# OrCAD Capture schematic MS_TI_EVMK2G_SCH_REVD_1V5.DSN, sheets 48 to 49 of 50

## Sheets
48 47. PMIC POWER CIRCUIT1: size C; title: PMIC POWER CIRCUIT 1
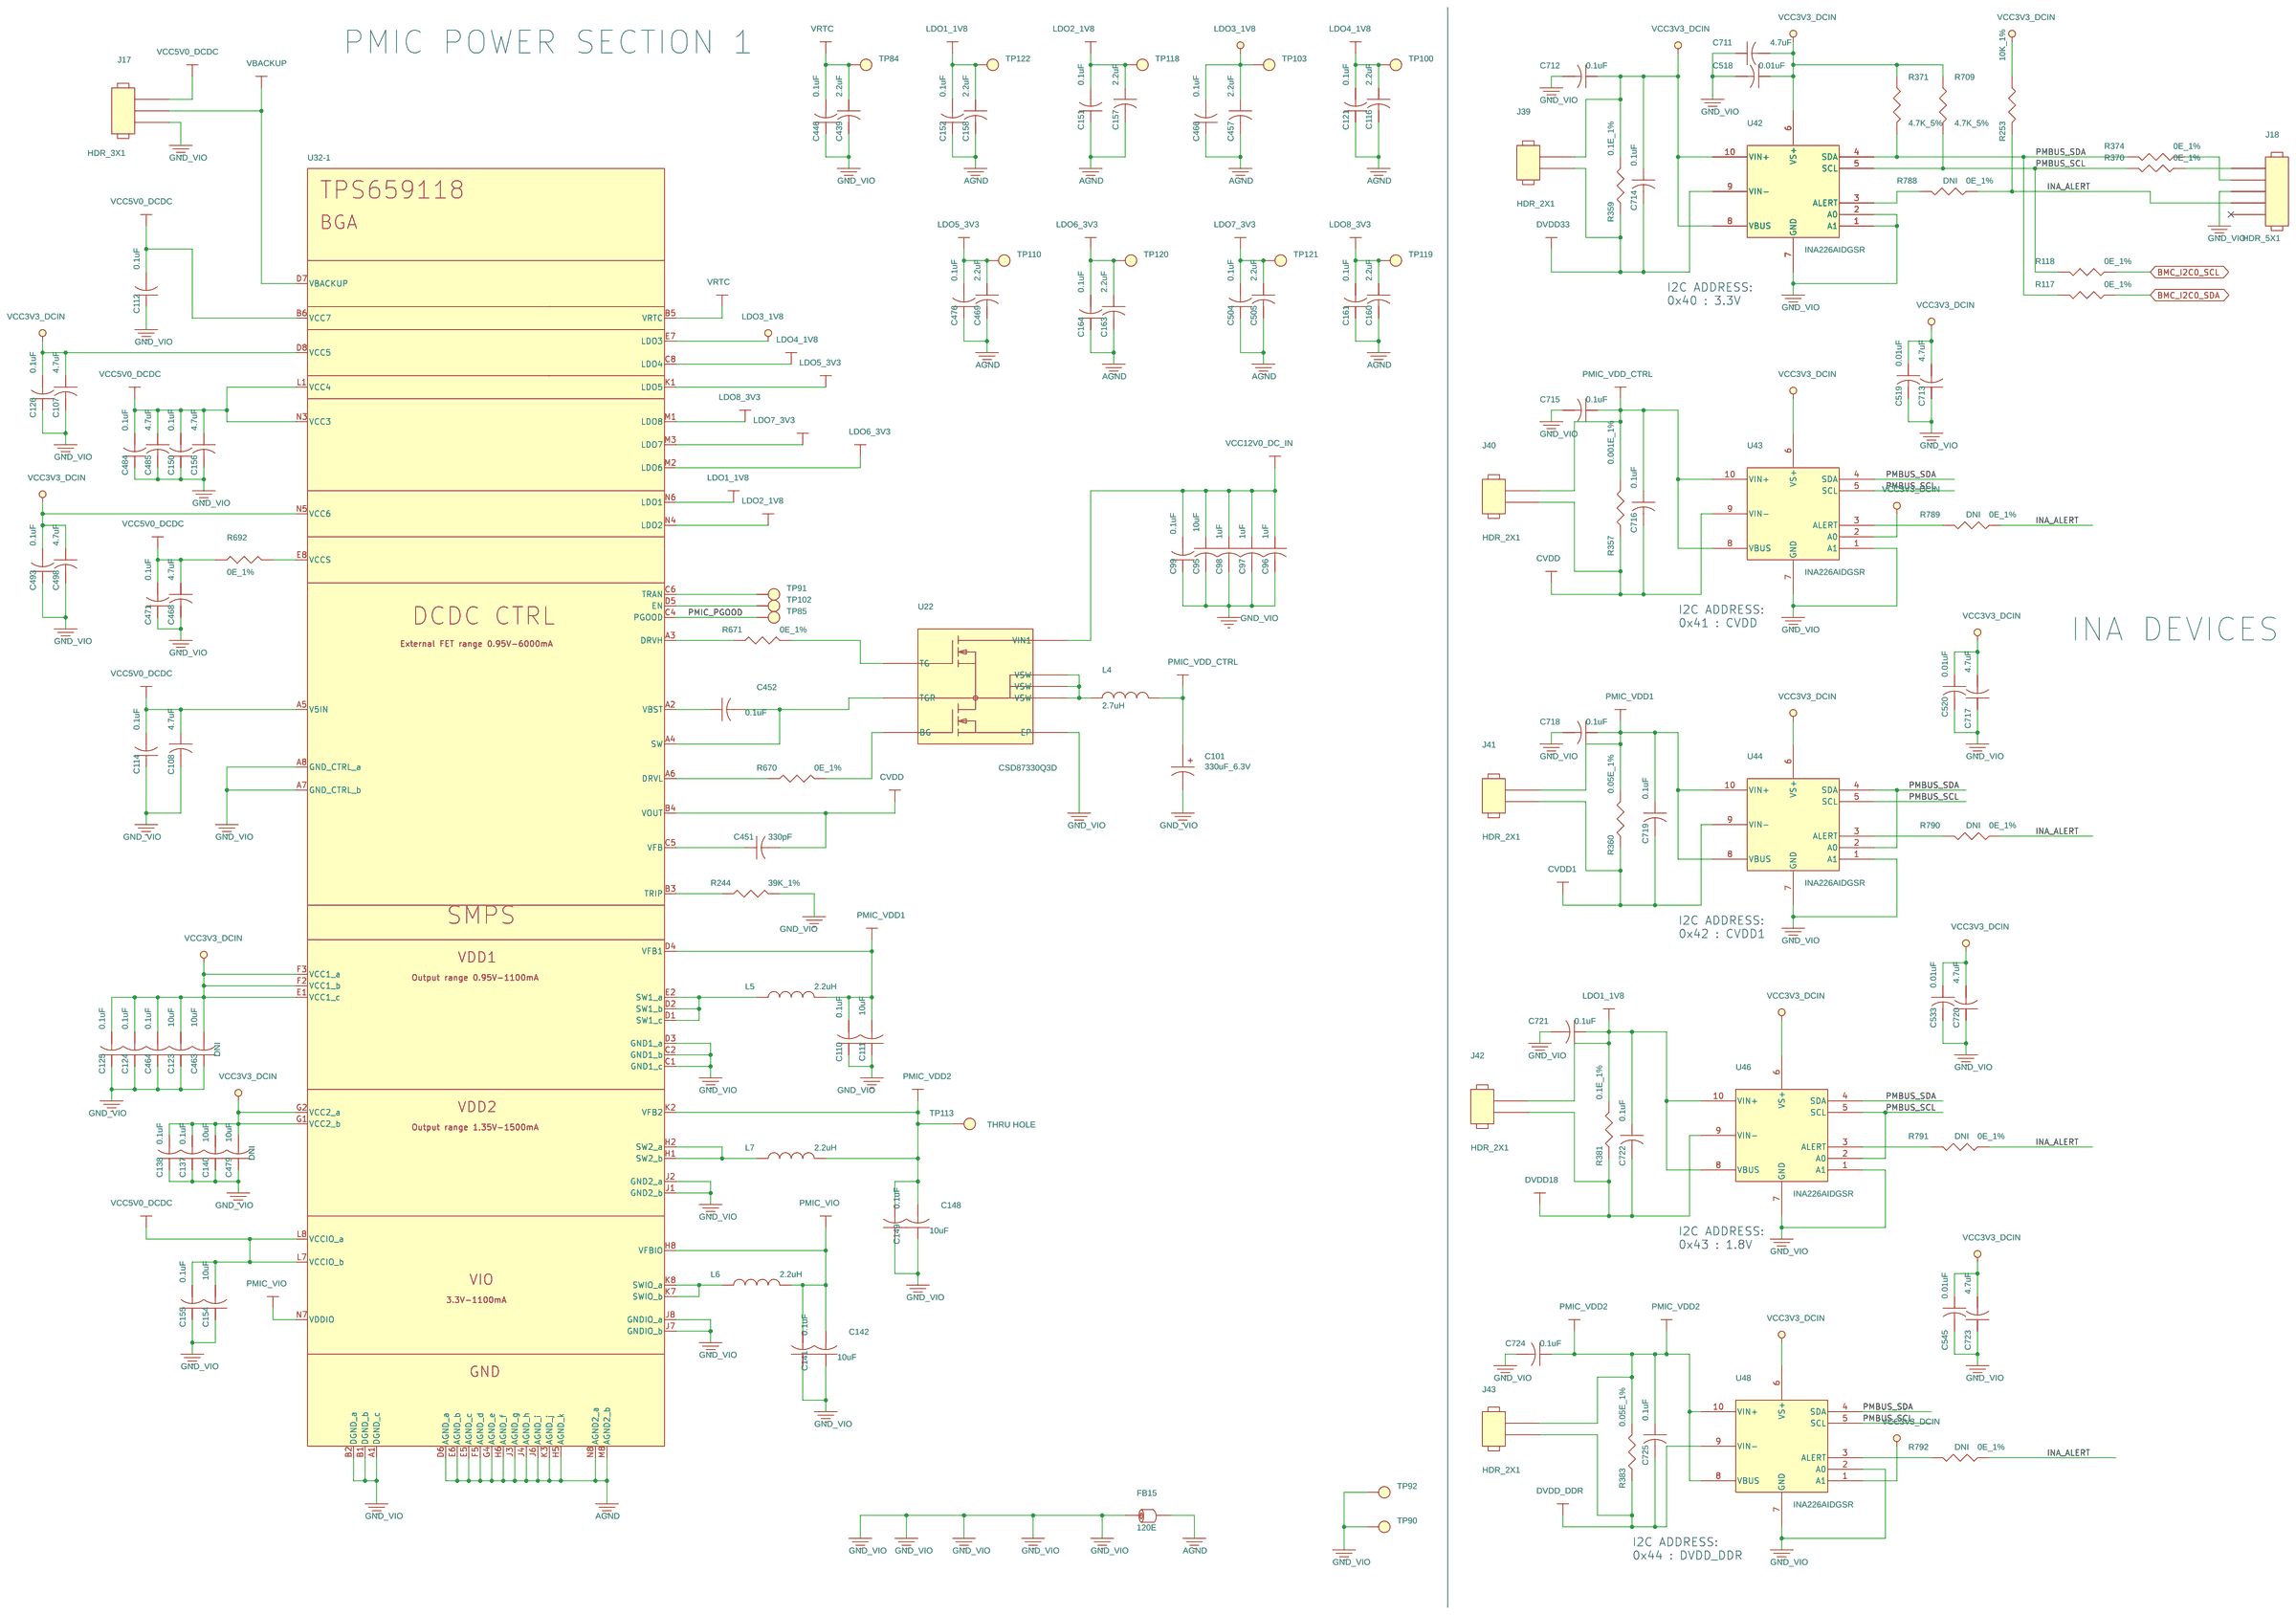
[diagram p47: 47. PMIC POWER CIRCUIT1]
49 48. PMIC POWER CIRCUIT2: size C; title: PMIC POWER CIRCUIT 2
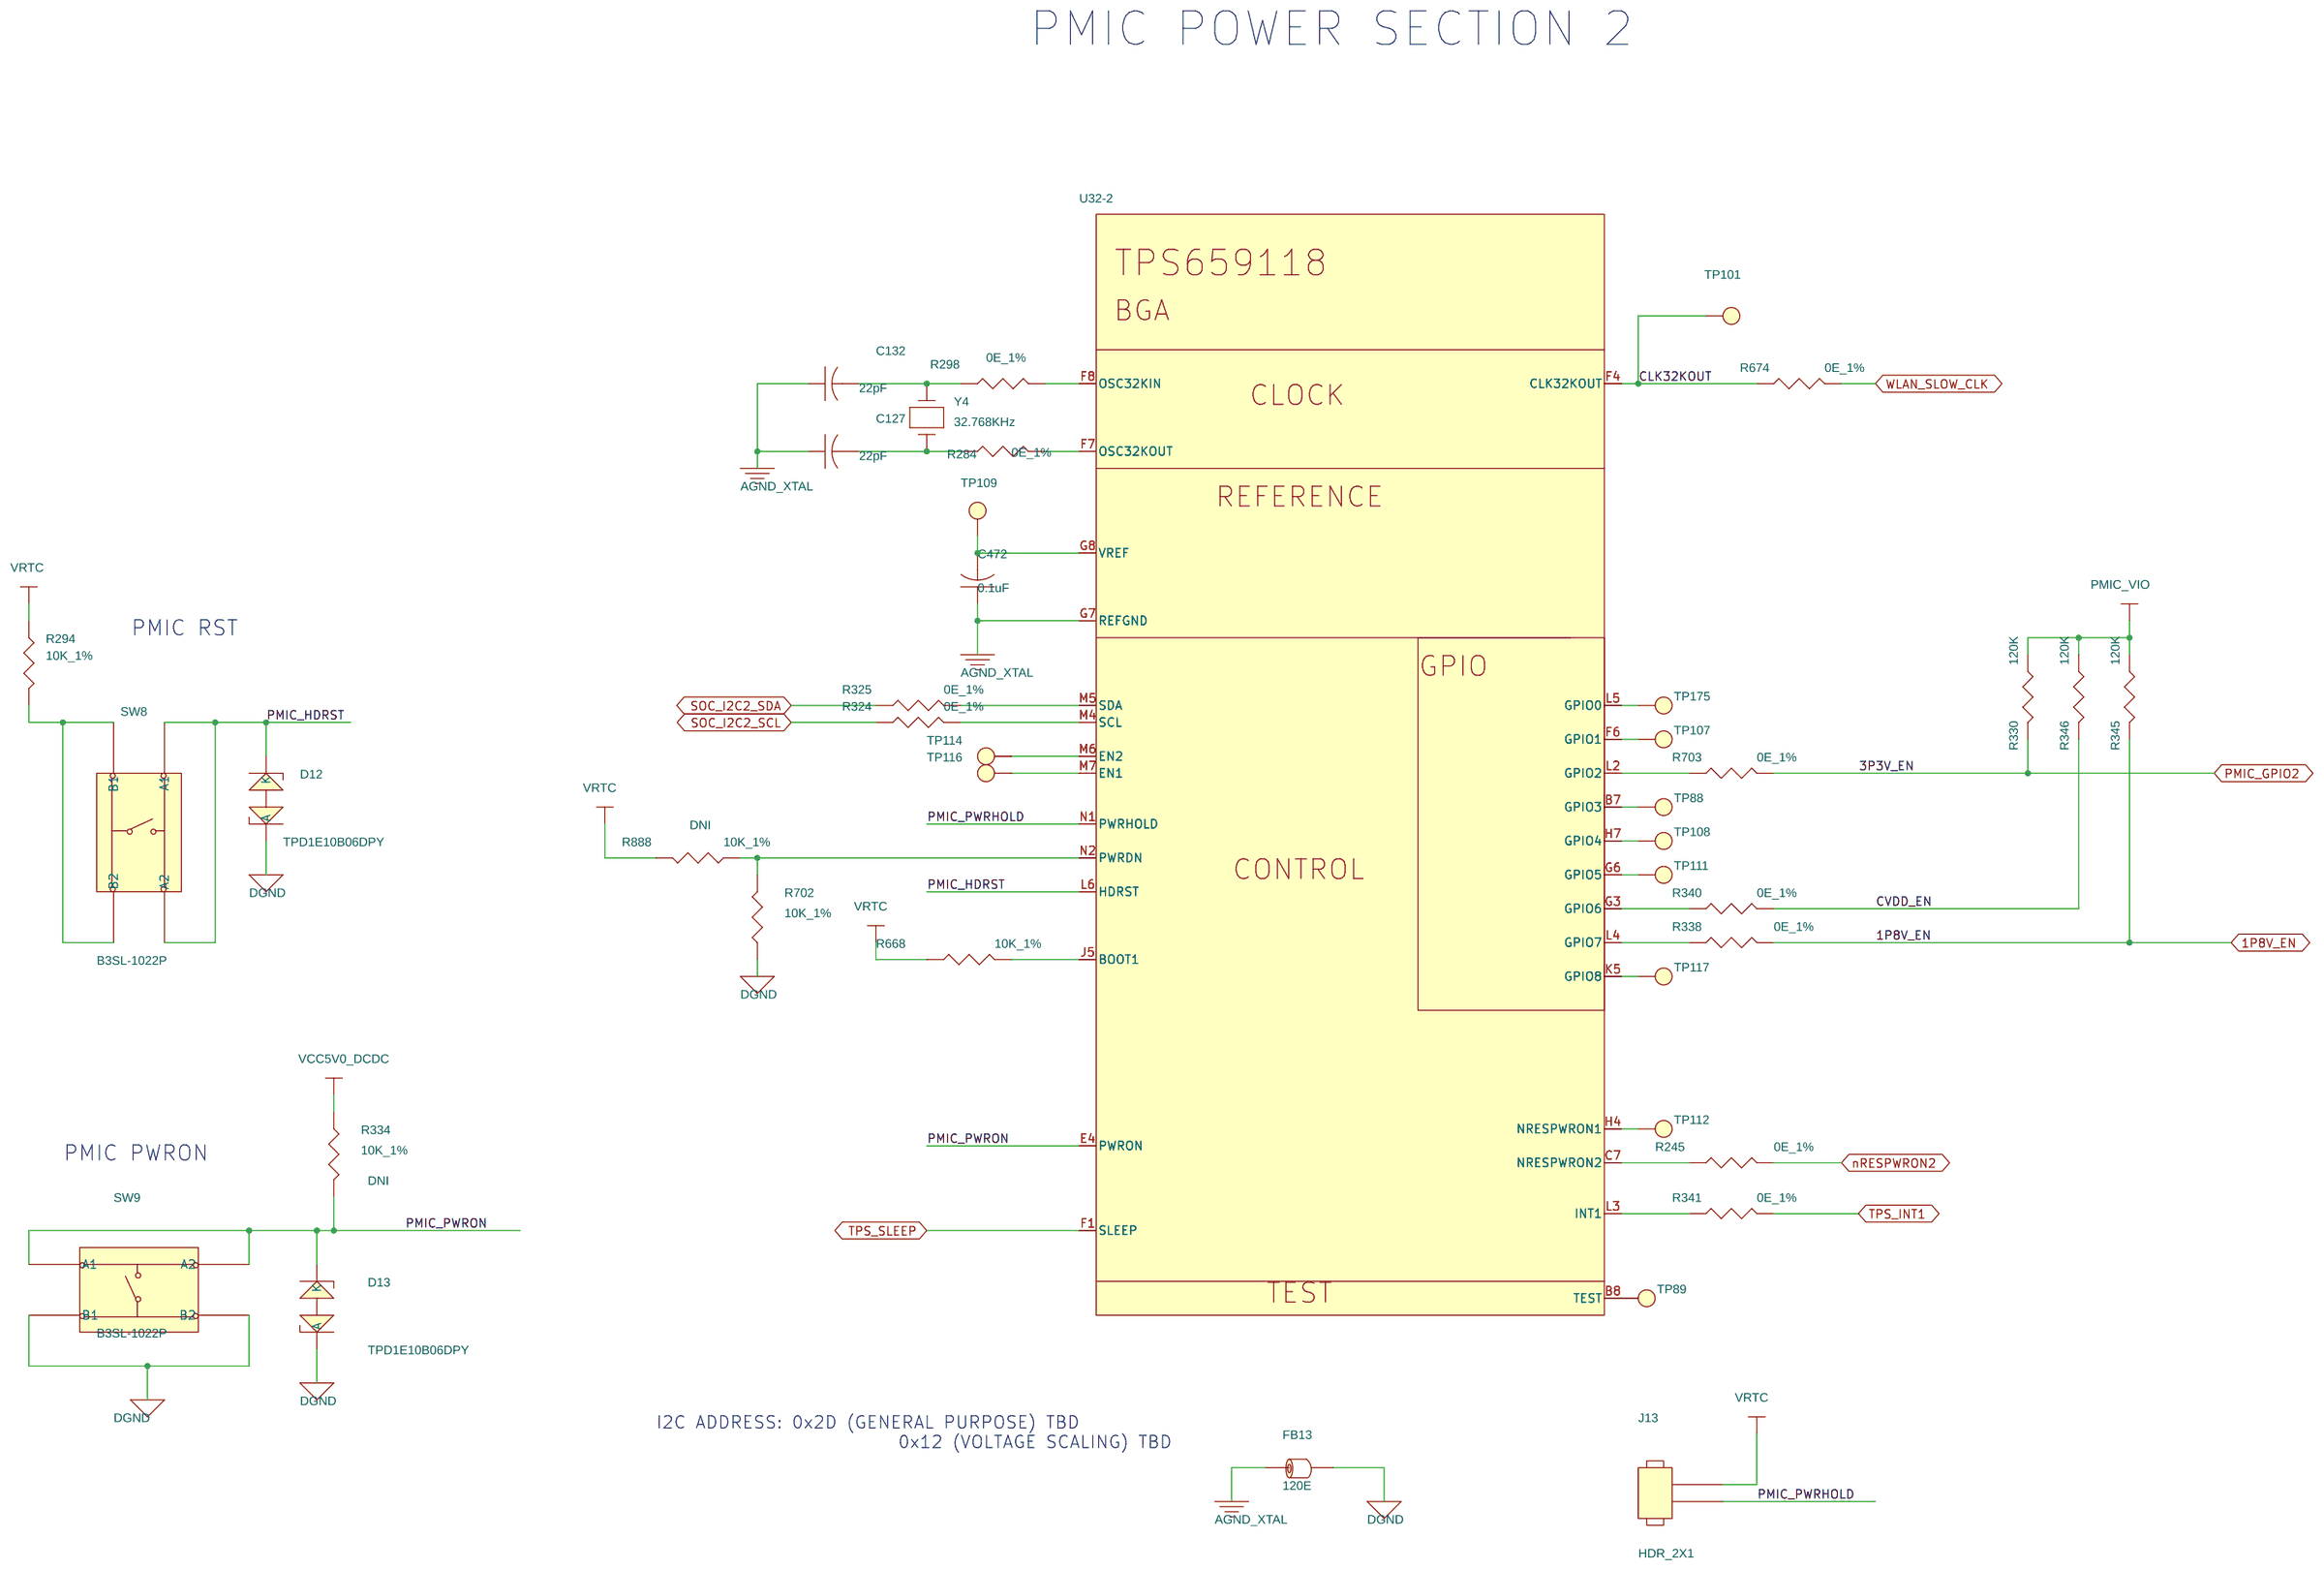
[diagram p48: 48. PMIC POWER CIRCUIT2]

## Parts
sheet 47. PMIC POWER CIRCUIT1
C95  10uF  [CAP1210]
C96  1uF  [CAP0603]
C97  1uF  [CAP0603]
C98  1uF  [CAP0603]
C99  0.1uF  [CAP0402]
C101  330uF_6.3V  [CAPT7343D]
C107  4.7uF  [CAP1206]
C108  4.7uF  [CAP1206]
C110  0.1uF  [CAP0402]
C111  10uF  [CAP0805]
C112  0.1uF  [CAP0402]
C114  0.1uF  [CAP0402]
C116  2.2uF  [CAP0402]
C121  0.1uF  [CAP0402]
C123  10uF  [CAP0805]
C124  0.1uF  [CAP0402]
C125  0.1uF  [CAP0402]
C126  0.1uF  [CAP0402]
C137  0.1uF  [CAP0402]
C138  0.1uF  [CAP0402]
C140  10uF  [CAP0805]
C141  0.1uF  [CAP0402]
C142  10uF  [CAP0805]
C148  10uF  [CAP0805]
C149  0.1uF  [CAP0402]
C150  0.1uF  [CAP0402]
C151  0.1uF  [CAP0402]
C152  0.1uF  [CAP0402]
C154  10uF  [CAP0805]
C155  0.1uF  [CAP0402]
C156  4.7uF  [CAP1206]
C157  2.2uF  [CAP0402]
C158  2.2uF  [CAP0402]
C160  2.2uF  [CAP0402]
C161  0.1uF  [CAP0402]
C163  2.2uF  [CAP0402]
C164  0.1uF  [CAP0402]
C439  2.2uF  [CAP0402]
C446  0.1uF  [CAP0402]
C451  330pF  [CAP0402]
C452  0.1uF  [CAP0402]
C457  2.2uF  [CAP0402]
C463  10uF  [CAP0805]
C464  0.1uF  [CAP0402]
C466  0.1uF  [CAP0402]
C468  4.7uF  [CAP1206]
C469  2.2uF  [CAP0402]
C471  0.1uF  [CAP0402]
C476  0.1uF  [CAP0402]
C479  10uF  [CAP0805]
C484  0.1uF  [CAP0402]
C485  4.7uF  [CAP1206]
C493  0.1uF  [CAP0402]
C498  4.7uF  [CAP1206]
C504  0.1uF  [CAP0402]
C505  2.2uF  [CAP0402]
C518  0.01uF  [CAP0402]
C519  0.01uF  [CAP0402]
C520  0.01uF  [CAP0402]
C533  0.01uF  [CAP0402]
C545  0.01uF  [CAP0402]
C711  4.7uF  [CAP0603]
C712  0.1uF  [CAP0402]
C713  4.7uF  [CAP0603]
C714  0.1uF  [CAP0402]
C715  0.1uF  [CAP0402]
C716  0.1uF  [CAP0402]
C717  4.7uF  [CAP0603]
C718  0.1uF  [CAP0402]
C719  0.1uF  [CAP0402]
C720  4.7uF  [CAP0603]
C721  0.1uF  [CAP0402]
C722  0.1uF  [CAP0402]
C723  4.7uF  [CAP0603]
C724  0.1uF  [CAP0402]
C725  0.1uF  [CAP0402]
FB15  120E  [IND0402]
J17  HDR_3X1  [HDR_3X1_100_S_T]
J18  HDR_5X1  [HDR_5X1_100_S_T]
J39  HDR_2X1  [HDR_2X1_100_S_T]
J40  HDR_2X1  [HDR_2X1_100_S_T]
J41  HDR_2X1  [HDR_2X1_100_S_T]
J42  HDR_2X1  [HDR_2X1_100_S_T]
J43  HDR_2X1  [HDR_2X1_100_S_T]
L4  2.7uH  [IND_XAL7030_315X315_SMD]
L5  2.2uH  [IND_VLCF5020T_205X210_SMD]
L6  2.2uH  [IND_VLCF5020T_205X210_SMD]
L7  2.2uH  [IND_VLCF5020T_205X210_SMD]
R117  0E_1%  [RES0402]
R118  0E_1%  [RES0402]
R244  39K_1%  [RES0603]
R253  10K_1%  [RES0402]
R357  0.001E_1%  [RES2725]
R359  0.1E_1%  [RES1210]
R360  0.05E_1%  [RES1812]
R370  0E_1%  [RES0402]
R371  4.7K_5%  [RES0402]
R374  0E_1%  [RES0402]
R381  0.1E_1%  [RES1210]
R383  0.05E_1%  [RES1812]
R670  0E_1%  [RES0402]
R671  0E_1%  [RES0402]
R692  0E_1%  [RES0402]
R709  4.7K_5%  [RES0402]
R788  0E_1%  [RES0402]
R789  0E_1%  [RES0402]
R790  0E_1%  [RES0402]
R791  0E_1%  [RES0402]
R792  0E_1%  [RES0402]
TP84  THRU HOLE  [TP_40X65]
TP85  THRU HOLE  [TP_40X65]
TP90  THRU HOLE  [TP_40X65]
TP91  THRU HOLE  [TP_40X65]
TP92  THRU HOLE  [TP_40X65]
TP100  THRU HOLE  [TP_40X65]
TP102  THRU HOLE  [TP_40X65]
TP103  THRU HOLE  [TP_40X65]
TP110  THRU HOLE  [TP_40X65]
TP113  THRU HOLE  [TP_40X80]
TP118  THRU HOLE  [TP_40X65]
TP119  THRU HOLE  [TP_40X65]
TP120  THRU HOLE  [TP_40X65]
TP121  THRU HOLE  [TP_40X65]
TP122  THRU HOLE  [TP_40X65]
U22  CSD87330Q3D  [SON8_25-59_130X130_TI]
U42  INA226AIDGSR  [MSOP10_19-68_120X120]
U43  INA226AIDGSR  [MSOP10_19-68_120X120]
U44  INA226AIDGSR  [MSOP10_19-68_120X120]
U46  INA226AIDGSR  [MSOP10_19-68_120X120]
U48  INA226AIDGSR  [MSOP10_19-68_120X120]
sheet 48. PMIC POWER CIRCUIT2
C127  22pF  [CAP0402]
C132  22pF  [CAP0402]
C472  0.1uF  [CAP0402]
D12  TPD1E10B06DPY  [DIO_DFN0402]
D13  TPD1E10B06DPY  [DIO_DFN0402]
FB13  120E  [IND0402]
J13  HDR_2X1  [HDR_2X1_100_S_T]
R245  0E_1%  [RES0402]
R284  0E_1%  [RES0402]
R294  10K_1%  [RES0402]
R298  0E_1%  [RES0402]
R324  0E_1%  [RES0402]
R325  0E_1%  [RES0402]
R330  120K  [RES0603]
R334  10K_1%  [RES0402]
R338  0E_1%  [RES0402]
R340  0E_1%  [RES0402]
R341  0E_1%  [RES0402]
R345  120K  [RES0603]
R346  120K  [RES0603]
R668  10K_1%  [RES0402]
R674  0E_1%  [RES0402]
R702  10K_1%  [RES0402]
R703  0E_1%  [RES0402]
R888  10K_1%  [RES0402]
SW8  B3SL-1022P  [SW4_EVQQ2_255X240_SMD]
SW9  B3SL-1022P  [SW4_EVQQ2_255X240_SMD]
TP88  THRU HOLE  [TP_40X65]
TP89  THRU HOLE  [TP_40X65]
TP101  THRU HOLE  [TP_40X65]
TP107  THRU HOLE  [TP_40X65]
TP108  THRU HOLE  [TP_40X65]
TP109  THRU HOLE  [TP_40X65]
TP111  THRU HOLE  [TP_40X65]
TP112  THRU HOLE  [TP_40X65]
TP114  THRU HOLE  [TP_40X65]
TP116  THRU HOLE  [TP_40X65]
TP117  THRU HOLE  [TP_40X65]
TP175  THRU HOLE  [TP_40X65]
U32  PTPS659113A2ZRC  [BGA98_25-59_360x240]  (sections -1,-2)
Y4  32.768KHz  [XTAL_FC-135_130X65_SMD]

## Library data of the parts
C95 = CAP: CAP CERAMIC 10uF 25V 20% X7R 1210; Chkd/date: SHREESHAIL/200707; Crtd /date: MAZHAR/180707; Custom_Duty: 15%; Customs_HS_Code: 85322990; Distributor_name: DIGIKEY; Distributor_part_number: 445-1434-1-ND; Height: 2.80MM; Mfr_name: TDK CORPORATION; Mfr_part_number: C3225X7R1E106M; Mistral Part No: 120009030191-R; Package: 1210; Part_type: CAPACITORS\CERAMIC; Project: REVA-IBMS; RoHS: RoHS; Tolerance: 20%; Voltage: 25V; Datasheet: Y:\MIS_DATABASE\DATASHEETS\CAPACITORS\TDK_CAP.PDF
C96-C98 = CAP: CAP CERAMIC 1uF 25V 10% X7R 0603; Chkd/date: BAVISH/040311; Crtd /date: MAZHAR/190111; Custom_Duty: 15%; Customs_HS_Code: 85322990; Distributor_name: DIGIKEY; Distributor_part_number: 490-5307-1-ND; Height: 0.90MM; Mfr_name: MURATA; Mfr_part_number: GRM188R71E105KA12D; Mistral Part No: 120011010017-R; Package: 0603; Part_type: CAPACITORS\CERAMIC; Project: ITS-PWR_CARD; RoHS: RoHS; Temperature: -55°C+125°C; Tolerance: 10%; Voltage: 25V; Wattage: NA; Weight: NA; Datasheet: Y:\MIS_DATABASE\DATASHEETS\CAPACITORS\GRM188SERIES.PDF
C99 C452 = CAP: CAP CERAMIC 0.1uF 50V 10% X7R 0402; Alternate_mfr_name_A: TDK CORPORATION; Alternate_mfr_part_number_A: CGA2B3X7R1H104K; Chkd/date: BAVISH/081111; Crtd /date: CHAITHANYA/051011; Custom_Duty: 15%; Customs_HS_Code: 85322990; Distributor_name: DIGIKEY; Distributor_name_A: DIGIKEY; Distributor_part_number: 445-5932-1-ND; Distributor_part_number_A: 445-6899-1-ND; Height: 0.55MM; Mfr_name: TDK CORPORATION; Mfr_part_number: C1005X7R1H104K; Mistral Part No: 120011100014-R; Package: 0402; Part_type: CAPACITORS\CERAMIC; Project: VP-4000-BASE-BOARD; RoHS: RoHS; Temperature: -55°C+125°C; Tolerance: 10%; Voltage: 50V; Wattage: NA; Weight: NA; Datasheet: Y:\MIS_DATABASE\DATASHEETS\CAPACITORS\C1005X7.PDF
C101 = CAP_POL: CAP TANTALUM 330uF 6.3V 20% ESR 10mE D7343-31; Chkd/date: MAZHAR/271210; Crtd /date: BAVISH/271210; Custom_Duty: 15%; Customs_HS_Code: 85322990; Distributor_name: DIGIKEY; Distributor_part_number: 399-4125-1-ND; Height: 3.10MM; Mfr_name: KEMET; Mfr_part_number: T530D337M006ATE010; Mistral Part No: 120010120021-R; Package: D7343; Part_type: CAPACITORS\TANTALUM; Project: CPCI3GADC_CARD; RoHS: RoHS; Temperature: -55°C+125°C; Tolerance: 20%; Voltage: 6.3V; Wattage: NA; Weight: NA; Datasheet: Y:\MIS_DATABASE\DATASHEETS\CAPACITORS\KEMET-T530.PDF
C107 C108 C156 C468 C485 C498 = CAP: CAP CERAMIC 4.7uF 25V 10% X5R 1206; Chkd/date: SHREESHAIL/291105; Crtd /date: MAZHAR/040505; Custom_Duty: 15%; Customs_HS_Code: 85322990; Distributor_name: DIGIKEY; Distributor_part_number: 478-1570-1-ND; Height: 1.50MM; Mfr_name: AVX CORPORATION; Mfr_part_number: 12063D475KAT2A; Mistral Part No: 120009030424-R; Package: 1206; Part_type: CAPACITORS\CERAMIC; Project: G4_SVGA; RoHS: RoHS; Tolerance: 10%; Voltage: 25V; Datasheet: Y:\MIS_DATABASE\DATASHEETS\CAPACITORS\AVX_MLC.PDF
C110 C112 C114 C121 C124-C126 C137 C138 C141 C149-C152 C155 C161 C164 C446 C464 C466 C471 C476 C484 C493 C504 C712 C714-C716 C718 C719 C721 C722 C724 C725 = CAP: CAP CERAMIC 0.1uF 25V -20% TO +80 Y5V 0402; Chkd/date: SHREESHAIL/301105; Crtd /date: MAZHAR/251005; Custom_Duty: 15%; Customs_HS_Code: 85322990; Distributor_name: DIGIKEY; Distributor_part_number: 490-3271-1-ND; Height: 0.55MM; Mfr_name: MURATA; Mfr_part_number: GRM155F51E104ZA01D; Mistral Part No: 120009030085; PART_NUMBER: EC01002; Package: 0402; Part_type: CAPACITORS\CERAMIC; Project: ADR; Taser_part_number: EC01002; Tolerance: -20% TO +80%; Voltage: 25V; Datasheet: Y:\MIS_DATABASE\DATASHEETS\CAPACITORS\GRM188SERIES.PDF
C111 C123 C140 C142 C148 C154 = CAP: CAP CERAMIC 10uF 16V 10% X5R 0805; Alternate_mfr_name_A: TAIYO YUDEN; Alternate_mfr_part_number_A: EMK212BJ106KG-T; Chkd/date: RAVI/020511; Crtd /date: BAVISH/290411; Custom_Duty: 15%; Customs_HS_Code: 85322990; Distributor_name: DIGIKEY; Distributor_name_A: DIGIKEY; Distributor_part_number: 478-5165-1-ND; Distributor_part_number_A: 587-1295-1-ND; Height: 1.40MM; Mfr_name: AVX CORPORATION; Mfr_part_number: 0805YD106KAT2A; Mistral Part No: 120011040011-R; Package: 0805; Part_type: CAPACITORS\CERAMIC; Project: AOD_POD-RF; RoHS: RoHS; Temperature: -55°C+85°C; Tolerance: 10%; Voltage: 16V; Wattage: NA; Weight: NA; Datasheet: Y:\MIS_DATABASE\DATASHEETS\CAPACITORS\AVX_CERAMIC.PDF
C116 C157 C158 C160 C163 C439 C457 C469 C505 = CAP: CAP CERAMIC 2.2uF 16V 10% X5R 0402; Chkd/date: JAGADISH/280314; Crtd /date: SARANYA/270314; Custom_Duty: 15%; Customs_HS_Code: 85322990; Distributor_name: DIGIKEY; Distributor_part_number: 445-9085-1-ND; Height: 0.55MM; Mfr_name: TDK CORPORATION; Mfr_part_number: C1005X5R1C225K050BC; Mistral Part No: 120014030032-R; Package: 0402; Part_type: CAPACITORS\CERAMIC; Project: DMP; RoHS: RoHS; Temperature: -55°C+85°C; Tolerance: 10%; Voltage: 16V; Wattage: NA; Weight: NA; Datasheet: Y:\MIS_DATABASE\DATASHEETS\CAPACITORS\TDK_CAP.PDF
C451 = CAP: CAP CERAMIC 330pF 50V 5% NP0 0402; Chkd/date: SHREESHAIL/290507; Crtd /date: MAZHAR/221206; Custom_Duty: 15%; Customs_HS_Code: 85322990; Distributor_name: DIGIKEY; Distributor_part_number: 490-1295-1-ND; Height: 0.55MM; Mfr_name: MURATA; Mfr_part_number: GRM1555C1H331JA01D; Mistral Part No: 120009030375; Package: 0402; Part_type: CAPACITORS\CERAMIC; Project: ADR1B; Tolerance: 5%; Voltage: 50V; Datasheet: Y:\MIS_DATABASE\DATASHEETS\CAPACITORS\GRM188SERIES.PDF
C463 C479 = CAP: CAP CERAMIC 10uF 16V 10% X5R 0805; Alternate_mfr_name_A: TAIYO YUDEN; Alternate_mfr_part_number_A: EMK212BJ106KG-T; Chkd/date: RAVI/020511; Crtd /date: BAVISH/290411; Custom_Duty: 15%; Customs_HS_Code: 85322990; Distributor_name: DIGIKEY; Distributor_name_A: DIGIKEY; Distributor_part_number: 478-5165-1-ND; Distributor_part_number_A: 587-1295-1-ND; Height: 1.40MM; Loading: DNI; Mfr_name: AVX CORPORATION; Mfr_part_number: 0805YD106KAT2A; Mistral Part No: 120011040011-R; Package: 0805; Part_type: CAPACITORS\CERAMIC; Project: AOD_POD-RF; RoHS: RoHS; Temperature: -55°C+85°C; Tolerance: 10%; Voltage: 16V; Wattage: NA; Weight: NA; Datasheet: Y:\MIS_DATABASE\DATASHEETS\CAPACITORS\AVX_CERAMIC.PDF
C518-C520 C533 C545 = CAP: CAP CERAMIC 0.01uF 16V 10% X7R 0402; Alternate_mfr_name_A: AVX CORPORATION; Alternate_mfr_name_B: KEMET; Alternate_mfr_name_D: TDK CORPORATION; Alternate_mfr_part_number_A: 0402YC103KAT2A; Alternate_mfr_part_number_B: C0402C103K4RACTU; Alternate_mfr_part_number_D: C1005X7R1C103K; Chkd/date: SHREESHAIL/180506; Crtd /date: MAZHAR/110506; Custom_Duty: 15%; Customs_HS_Code: 85322990; Distributor_name: DIGIKEY; Distributor_name_A: DIGIKEY; Distributor_name_B: DIGIKEY; Distributor_name_D: DIGIKEY; Distributor_part_number: PCC103BQCT-ND; Distributor_part_number_A: 478-1114-1-ND; Distributor_part_number_B: 399-1038-1-ND; Distributor_part_number_D: 445-1262-1-ND; Height: 0.55MM; Mfr_name: PANASONIC-ECG; Mfr_part_number: ECJ-0EB1C103K; Mistral Part No: 120009030032-R; Package: 0402; Part_type: CAPACITORS\CERAMIC; Project: VOCERA; RoHS: RoHS; Tolerance: 10%; Voltage: 16V; Datasheet: Y:\MIS_DATABASE\DATASHEETS\CAPACITORS\PAN-ECJ.PDF
C711 C713 C717 C720 C723 = CAP: CAP CERAMIC 4.7uF 16V 10% X5R 0603; Chkd/date: VASANTHA/230714; Crtd /date: BAVISH/060511; Custom_Duty: 15%; Customs_HS_Code: 85322990; Distributor_name: DIGIKEY; Distributor_part_number: 587-2786-1-ND; Height: 0.90MM; Mfr_name: TAIYO YUDEN; Mfr_part_number: EMK107ABJ475KA-T; Mistral Part No: 120011050004-R; Package: 0603; Part_type: CAPACITORS\CERAMIC; Project: HMC; RoHS: RoHS; Temperature: -55°C+85°C; Tolerance: 10%; Voltage: 16V; Wattage: NA; Weight: NA; Datasheet: Y:\MIS_DATABASE\DATASHEETS\CAPACITORS\EMK107.PDF
FB13 FB15 = INDUCTOR_FERRITE: IND BEAD CHIP 120E 1.2A 0402; Chkd/date: ASHOK/240212; Crtd /date: BAVISH/060711; Custom_Duty: 24%; Customs_HS_Code: 85437099; Distributor_name: DIGIKEY; Distributor_part_number: 445-2981-1-ND; Height: 0.55MM; Mfr_name: TDK CORPORATION; Mfr_part_number: MPZ1005S121C; Mistral Part No: 130011070007-R; Package: 0402; Part_type: INDUCTOR; Project: SVDU; RoHS: RoHS; Temperature: -40°C+85°C; Tolerance: NA; Voltage: NA; Wattage: NA; Weight: 1mg; Datasheet: Y:\MIS_DATABASE\DATASHEETS\DISCRETES\INDUCTORS\MPZ1005.PDF
J17 = HEADER_3X1: CON HDR 3X1 2.54MM PITCH ST TH; Chkd/date: MAZHAR/100311; Crtd /date: BAVISH/160211; Custom_Duty: 24%; Customs_HS_Code: 85369090; Distributor_name: DIGIKEY; Distributor_part_number: A26545-ND; Height: 10.74MM; Mfr_name: TYCO ELECTRONICS; Mfr_part_number: 87224-3; Mistral Part No: 150011020004-R; Package: THRU-HOLE; Part_type: CONNECTOR\HEADERS; Project: OMAPL1_PEC20; RoHS: RoHS; Temperature: NA; Tolerance: NA; Voltage: NA; Wattage: NA; Weight: NA; Datasheet: Y:\MIS_DATABASE\DATASHEETS\CONNECTORS\87224.PDF
J18 = HEADER_5X1: CON HDR 5X1 2.54MM PITCH ST TH; Alternate_mfr_name_A: SAMTEC; Alternate_mfr_part_number_A: TSW-105-23-T-S; Chkd/date: SHREESHAIL/130206; Crtd /date: MAZHAR/280405; Custom_Duty: 24%; Customs_HS_Code: 85369090; Distributor_name: DIGIKEY; Distributor_part_number: WM4003-ND; Height: 10.79MM; Mfr_name: MOLEX; Mfr_part_number: 22-03-2051; Mistral Part No: 150009030262; Package: THRU-HOLE; Part_type: CONNECTOR\HEADERS; Project: HSWD; Datasheet: Y:\MIS_DATABASE\DATASHEETS\CONNECTORS\HEADER_X4030.PDF
J13 J39-J43 = HEADER_2X1: CON HDR 2X1 2.54MM PITCH ST TH; Alternate_mfr_name_A: SULLINS ELECTRONICS; Alternate_mfr_name_B: SAMTEC; Alternate_mfr_name_C: HANTRONIX; Alternate_mfr_part_number_A: PZC02SAAN; Alternate_mfr_part_number_B: TLW-102-06-G-S; Alternate_mfr_part_number_C: HDM20216L; Chkd/date: SHREESHAIL/140206; Crtd /date: MAZHAR/280405; Custom_Duty: 24%; Customs_HS_Code: 85369090; Distributor_name: DIGIKEY; Distributor_part_number: WM4000-ND; Height: 10.79MM; Mfr_name: MOLEX; Mfr_part_number: 22-03-2021; Mistral Part No: 150009030246-R; Package: THRU-HOLE; Part_type: CONNECTOR\HEADERS; Project: FPGA EXTENDER CARD; RoHS: RoHS; Datasheet: Y:\MIS_DATABASE\DATASHEETS\CONNECTORS\HEADER_X4030.PDF
L4 = INDUCTOR: IND POWER 2.7uH 20% 12.8A SMD; Chkd/date: ASHOK/240212; Crtd /date: CHAITHANYA/121011; Custom_Duty: 24%; Customs_HS_Code: 85437099; Distributor_name: NA; Distributor_part_number: NA; Height: 3.10MM; Mfr_name: COIL CRAFT; Mfr_part_number: XAL7030-272MEB; Mistral Part No: 130011100015-R; Package: SMD; Project: DM385EVM_BASE-BOARD; RoHS: RoHS; Temperature: -40°C+90°C; Tolerance: 20%; Voltage: NA; Wattage: NA; Weight: 0.86g; Datasheet: Y:\MIS_DATABASE\DATASHEETS\DISCRETES\INDUCTORS\XAL7030.PDF
L5-L7 = INDUCTOR: IND POWER 2.2uH 2.6A 30% SMD; Chkd/date: Ravi/041010; Crtd /date: MUDDU/030610; Custom_Duty: 24%; Customs_HS_Code: 85437099; Distributor_name: DIGIKEY; Distributor_part_number: 445-4557-1-ND; Height: 2.00MM; Mfr_name: TDK CORPORATION; Mfr_part_number: VLCF5020T-2R2N2R6-3; Mistral Part No: 130010060006-R; Package: SMD; Project: SHIVA; RoHS: RoHS; Temperature: -40°C+105°C; Tolerance: 30%; Weight: NA; Datasheet: Y:\MIS_DATABASE\DATASHEETS\DISCRETES\INDUCTORS\VLCF5020T-2R2N2R6-3.PDF
R117 R118 R245 R284 R298 R324 R325 R338 R340 R341 R370 R374 R670 R671 R674 R692 R703 = RESISTOR: RES 0E 1/16W 1% 0402; Chkd/date: MAZHAR/220709; Crtd /date: USMAN/270109; Custom_Duty: 15%; Customs_HS_Code: 85332119; Distributor_name: NA; Distributor_part_number: NA; Height: 0.40MM; Mfr_name: YAGEO AMERICA; Mfr_part_number: RC0402FR-070RL; Mistral Part No: 110009030085-P; Package: 0402; Part_type: RESISTORS\FIXED; Project: OMAP_EVM; RoHS: Pb-Free; Tolerance: 1%; Wattage: 1/16W; Datasheet: Y:\MIS_DATABASE\DATASHEETS\RESISTORS\CRCW0603.PDF
R244 = RESISTOR: RES 39K 1/10W 1% 0603; Chkd/date: MAZHAR/290508; Crtd /date: USMAN/260508; Custom_Duty: 15%; Customs_HS_Code: 85332119; Distributor_name: DIGIKEY; Distributor_part_number: P39.0KHCT-ND; Height: 0.55MM; Mfr_name: PANASONIC-ECG; Mfr_part_number: ERJ-3EKF3902V; Mistral Part No: 110009030760-R; Package: 0603; Part_type: RESISTORS\FIXED; Project: REVA-IBMS; RoHS: RoHS; Tolerance: 1%; Wattage: 1/10W; Datasheet: Y:\MIS_DATABASE\DATASHEETS\RESISTORS\PAN_ERJ.PDF
R253 R294 R668 R702 = RESISTOR: RES 10K 1/16W 1% 0402; Alternate_mfr_name_A: AVX CORPORATION; Alternate_mfr_name_B: PANASONIC-ECG-ECG; Alternate_mfr_name_C: YAGEO AMERICA; Alternate_mfr_name_D: VISHAY; Alternate_mfr_part_number_A: CR05-103F-H; Alternate_mfr_part_number_B: ERJ-2RKF1002X; Alternate_mfr_part_number_C: 9C04021A1002FLHF3; Alternate_mfr_part_number_D: CRCW040210K0FKED; Chkd/date: SHREESHAIL/310506; Crtd /date: GEETHA/290506; Custom_Duty: 15%; Customs_HS_Code: 85332119; Distributor_name: DIGIKEY; Distributor_name_A: NA; Distributor_name_B: DIGIKEY; Distributor_name_C: DIGIKEY; Distributor_name_D: DIGIKEY; Distributor_part_number: 311-10.0KLRTR-ND; Distributor_part_number_A: NA; Distributor_part_number_B: P10.0KLCT-ND; Distributor_part_number_C: 311-10.0KLCT-ND; Distributor_part_number_D: 541-10.0KLCT-ND; Height: 0.40MM; Mfr_name: YAGEO AMERICA; Mfr_part_number: RC0402FR-0710KL; Mistral Part No: 110009030220-P; Package: 0402; Part_type: RESISTORS\FIXED; Project: VOCERA; RoHS: Pb-Free; Tolerance: 1%; Wattage: 1/16W; Datasheet: Y:\MIS_DATABASE\DATASHEETS\RESISTORS\YAGEO-RC0402.PDF
R357 = RESISTOR: RES 0.001E 4W 1% 2725; Chkd/date: SUHAS/240910; Crtd /date: MUDDU/100710; Custom_Duty: 15%; Customs_HS_Code: 85332119; Distributor_name: DIGIKEY; Distributor_part_number: CSS2725FT1L00CT-ND; Height: 1.09MM; Mfr_name: STACKPOLE ELECTRONICS; Mfr_part_number: CSS2725FT1L00; Mistral Part No: 110010070062-R; Package: 2725; Part_type: RESISTORS\FIXED; Project: CENTAURUS; RoHS: RoHS; Temperature: -65°C+275°C; Tolerance: 1%; Voltage: NA; Wattage: 4W; Weight: NA; Datasheet: Y:\MIS_DATABASE\DATASHEETS\RESISTORS\CSS_RES.PDF
R359 R381 = RESISTOR: RES 0.1E 1/4W 1% 1210; Chkd/date: SHREESHAIL/141205; Crtd /date: MAZHAR/050405; Custom_Duty: 15%; Customs_HS_Code: 85332119; Distributor_name: DIGIKEY; Distributor_part_number: P100NACT-ND; Height: 0.70MM; Mfr_name: PANASONIC-ECG; Mfr_part_number: ERJ-L14KF10CU; Mistral Part No: 110009030066-R; Package: 1210; Part_type: RESISTORS\FIXED; Project: HSWD; RoHS: RoHS; Tolerance: 1%; Wattage: 1/4W; Datasheet: Y:\MIS_DATABASE\DATASHEETS\RESISTORS\ERJL.PDF
R360 R383 = RESISTOR: RES 0.05E 1/2W 1% 1812; Chkd/date: MAZHAR/191208; Crtd /date: USMAN/261108; Custom_Duty: 15%; Customs_HS_Code: 85332119; Distributor_name: DIGIKEY; Distributor_part_number: P50NBCT-ND; Height: 0.70MM; Mfr_name: PANASONIC-ECG; Mfr_part_number: ERJ-L12KF50MU; Mistral Part No: 110009030058-R; Package: 1812; Part_type: RESISTORS\FIXED; Project: KHAN_MAIN; RoHS: RoHS; Tolerance: 1%; Wattage: 1/2W; Datasheet: Y:\MIS_DATABASE\DATASHEETS\RESISTORS\ERJL.PDF
R371 R709 = RESISTOR: RES 4.7K 1/16W 5% 0402; Chkd/date: VASANTHA/190614; Crtd /date: NAVEED/160614; Custom_Duty: 15%; Customs_HS_Code: 85332119; Distributor_name: DIGIKEY; Distributor_part_number: RMCF0402JT4K70CT-ND; Height: 0.40MM; Mfr_name: STACKPOLE ELECTRONICS; Mfr_part_number: RMCF0402JT4K70; Mistral Part No: 110014060028-R; Package: 0402; Part_type: RESISTORS\FIXED; Project: AEGIS_POM; RoHS: RoHS; Temperature: -55°C+155°C; Tolerance: 5%; Voltage: NA; Wattage: 1/16W; Weight: NA; Datasheet: Y:\MIS_DATABASE\DATASHEETS\RESISTORS\RMCF-SERIES1.PDF
R788-R792 = RESISTOR: RES 0E 1/16W 1% 0402; Chkd/date: MAZHAR/220709; Crtd /date: USMAN/270109; Custom_Duty: 15%; Customs_HS_Code: 85332119; Distributor_name: NA; Distributor_part_number: NA; Height: 0.40MM; Loading: DNI; Mfr_name: YAGEO AMERICA; Mfr_part_number: RC0402FR-070RL; Mistral Part No: 110009030085-P; Package: 0402; Part_type: RESISTORS\FIXED; Project: OMAP_EVM; RoHS: Pb-Free; Tolerance: 1%; Wattage: 1/16W; Datasheet: Y:\MIS_DATABASE\DATASHEETS\RESISTORS\CRCW0603.PDF
TP84 TP85 TP88-TP92 TP100-TP103 TP107-TP112 TP114 TP116-TP122 TP175 = TESTPOINT: TESTPOINT 1.0MM DRILL PTH; Chkd/date: MAZHAR/271211; Crtd /date: SHREESHAIL/041005; Distributor_name: NA; Distributor_part_number: NA; Height: NA; Mfr_name: LOCAL; Mistral Part No: 130009030938; Package: THRU-HOLE; Part_type: MISC\TESTPOINT; Project: HSE; Datasheet: NA
TP113 = TESTPOINT: TESTPOINT 1.0MM DRILL PTH; Chkd/date: BAVISH/040311; Crtd /date: MAZHAR/210307; Distributor_name: NA; Distributor_part_number: NA; Height: NA; Mfr_name: LOCAL; Mistral Part No: 130009030934; Package: THRU-HOLE; Part_type: MISC\TESTPOINT; Project: PNAV; Temperature: NA; Tolerance: NA; Voltage: NA; Wattage: NA; Weight: NA; Datasheet: NA
U22 = MOSFET_CSD87330Q3D: IC SYNCHRONOUS BUCK NEXFET POWER BLOCK SON8; Chkd/date: NAVEED/220814; Crtd /date: VASANTHA/100714; Custom_Duty: 15%; Customs_HS_Code: 85423100; Distributor_name: DIGIKEY; Distributor_part_number: 296-29660-1-ND; Height: 1.50MM; Mfr_name: TEXAS INSTRUMENTS; Mistral Part No: 142014070002-R; Package: SON8; Part_type: ICS\POWER\MOSFET; Project: INFOCUS_VIDEO_PHONE; RoHS: RoHS; Temperature: -55°C+150°C; Tolerance: NA; Voltage: NA; Wattage: NA; Weight: NA; Datasheet: Y:\MIS_DATABASE\DATASHEETS\DISCRETES\TRANSISTORS_FETS\CSD87330Q3D.PDF
U42-U44 U46 U48 = INA226AIDGS_MSOP10: IC BI-DIRECTIONAL CURRENT MONITER MSOP10; Chkd/date: NAVEED/060115; Crtd /date: BAVISH/160811; Custom_Duty: 15%; Customs_HS_Code: 85423100; Distributor_name: DIGIKEY; Distributor_part_number: 296-29034-1-ND; Height: 1.10MM; Mfr_name: TEXAS INSTRUMENTS; Mistral Part No: 141011080019-R; Package: MSOP10; Part_type: ICS\INTERFACE; Project: DM385EVM_BASE-BOARD; RoHS: RoHS; Temperature: -40°C+125°C; Tolerance: NA; Voltage: NA; Wattage: NA; Weight: NA; Datasheet: Y:\MIS_DATABASE\DATASHEETS\ICS\INTERFACE\INA226.PDF
C127 C132 = CAP: CAP CERAMIC 22pF 25V 5% NP0 0402; Chkd/date: SHREESHAIL/291105; Crtd /date: MAZHAR/040505; Custom_Duty: 15%; Customs_HS_Code: 85322990; Distributor_name: DIGIKEY; Distributor_part_number: 04023A220JAT2A-ND; Height: 0.60MM; Mfr_name: AVX CORPORATION; Mfr_part_number: 04023A220JAT2A; Mistral Part No: 120009030322-R; Package: 0402; Part_type: CAPACITORS\CERAMIC; Project: TELEMATICS-02; RoHS: RoHS; Tolerance: 5%; Voltage: 25V; Datasheet: Y:\MIS_DATABASE\DATASHEETS\CAPACITORS\AVX_MLC.PDF
C472 = CAP: CAP CERAMIC 0.1uF 25V -20% TO +80 Y5V 0402; Chkd/date: SHREESHAIL/301105; Crtd /date: MAZHAR/251005; Custom_Duty: 15%; Customs_HS_Code: 85322990; Distributor_name: DIGIKEY; Distributor_part_number: 490-3271-1-ND; Height: 0.55MM; Mfr_name: MURATA; Mfr_part_number: GRM155F51E104ZA01D; Mistral Part No: 120009030085; Package: 0402; Part_type: CAPACITORS\CERAMIC; Project: ADR; Tolerance: -20% TO +80%; Voltage: 25V; Datasheet: Y:\MIS_DATABASE\DATASHEETS\CAPACITORS\GRM188SERIES.PDF
D12 D13 = DIODE_PESD: DIODE 1CH ESD PROTECTION SMD(0402); Chkd/date: USMAN/021214; Crtd /date: VASANTHA/181114; Custom_Duty: 15%; Customs_HS_Code: 85423100; Distributor_name: DIGIKEY; Distributor_part_number: 296-30406-1-ND; Height: 0.45MM; Mfr_name: TEXAS INSTRUMENTS; Mistral Part No: 130014110022-R; Package: SMD; Part_type: DIODE\MISC; Project: GALILEO_EVM; RoHS: RoHS; Temperature: -40°C+125°C; Tolerance: NA; Voltage: NA; Wattage: NA; Weight: NA; Datasheet: Y:\MIS_DATABASE\DATASHEETS\ICS\INTERFACE\TPD1E10B06.PDF
R330 R345 R346 = RESISTOR: RES 120K 1/10W 5% 0603; Chkd/date: MAZHAR/290508; Crtd /date: MAZHAR/170907; Custom_Duty: 15%; Customs_HS_Code: 85332119; Distributor_name: DIGIKEY; Distributor_part_number: P120KGCT-ND; Height: 0.55MM; Mfr_name: PANASONIC-ECG; Mfr_part_number: ERJ-3GEYJ124V; Mistral Part No: 110009030260-R; Package: 0603; Part_type: RESISTORS\FIXED; Project: SMART VIEW_NVR; RoHS: RoHS; Tolerance: 5%; Wattage: 1/10W; Datasheet: Y:\MIS_DATABASE\DATASHEETS\RESISTORS\PAN-ERJ-3GE.PDF
R334 R888 = RESISTOR: RES 10K 1/16W 1% 0402; Alternate_mfr_name_A: AVX CORPORATION; Alternate_mfr_name_B: PANASONIC-ECG-ECG; Alternate_mfr_name_C: YAGEO AMERICA; Alternate_mfr_name_D: VISHAY; Alternate_mfr_part_number_A: CR05-103F-H; Alternate_mfr_part_number_B: ERJ-2RKF1002X; Alternate_mfr_part_number_C: 9C04021A1002FLHF3; Alternate_mfr_part_number_D: CRCW040210K0FKED; Chkd/date: SHREESHAIL/310506; Crtd /date: GEETHA/290506; Custom_Duty: 15%; Customs_HS_Code: 85332119; Distributor_name: DIGIKEY; Distributor_name_A: NA; Distributor_name_B: DIGIKEY; Distributor_name_C: DIGIKEY; Distributor_name_D: DIGIKEY; Distributor_part_number: 311-10.0KLRTR-ND; Distributor_part_number_A: NA; Distributor_part_number_B: P10.0KLCT-ND; Distributor_part_number_C: 311-10.0KLCT-ND; Distributor_part_number_D: 541-10.0KLCT-ND; Height: 0.40MM; Loading: DNI; Mfr_name: YAGEO AMERICA; Mfr_part_number: RC0402FR-0710KL; Mistral Part No: 110009030220-P; Package: 0402; Part_type: RESISTORS\FIXED; Project: VOCERA; RoHS: Pb-Free; Tolerance: 1%; Wattage: 1/16W; Datasheet: Y:\MIS_DATABASE\DATASHEETS\RESISTORS\YAGEO-RC0402.PDF
SW8 SW9 = SWTACT_1_EVQQ2: TACTILE SWITCH SPST-NO SMD; Chkd/date: VASANTHA/140714; Crtd /date: NAVEED/170614; Custom_Duty: 24%; Customs_HS_Code: 85369090; Distributor_name: DIGIKEY; Distributor_part_number: SW1065CT-ND; Height: 5.10MM; Mfr_name: OMRON; Mistral Part No: 130014060032-R; Package: SMD; Part_type: ELECTRO-MECHANICAL\SWITCH; Project: AEGIS_POM; RoHS: RoHS; Temperature: -25°C+90°C; Tolerance: NA; Voltage: NA; Wattage: NA; Weight: NA; Datasheet: Y:\MIS_DATABASE\DATASHEETS\MISC\SWITCHES\B3SL.PDF
U32 = TPS659113A2_BGA98_2: IC POWER MANAGEMENT BGA98; Chkd/date: RAGESH/080311; Crtd /date: MUDDU/170610; Custom_Duty: 15%; Customs_HS_Code: 85423100; Distributor_name: NA; Distributor_part_number: NA; Height: 1.00MM; Mfr_name: TEXAS INSTRUMENTS; Mistral Part No: 142010060015-R; Package: BGA98; Part_type: ICS\POWER; Project: CENTAURUS; Remarks: Part# TPS659113 is replaced with new part# PTPS659113A2ZRC. Symbol and footprint name changed (BAVISH/220411), RoHS upgraded; RoHS: RoHS; Temperature: -40°C+85°C; Tolerance: NA; Voltage: NA; Wattage: NA; Weight: NA; Datasheet: Y:\MIS_DATABASE\DATASHEETS\ICS\POWER\TPS659113.PDF
Y4 = CRY: CRY 32.768KHz SMD; Chkd/date: SHREESHAIL/211205; Crtd /date: MAZHAR/061005; Custom_Duty: 24%; Customs_HS_Code: 85439000; Distributor_name: DIGIKEY; Distributor_part_number: SE2413CT-ND; Height: 0.90MM; Mfr_name: CRYSTAL UNITS; Mfr_part_number: FC-135 32.7680KA-A3; Mistral Part No: 130009030095-P; Package: SMD; Part_type: CRYSTAL; Project: J30; RoHS: Pb-Free; Datasheet: Y:\MIS_DATABASE\DATASHEETS\MISC\CRY_OSC\FC-135.PDF

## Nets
AGND: C116.2 C121.1 C151.1 C152.1 C157.2 C158.2 C160.2 C161.1 C163.2 C164.1 C457.2 C466.1 C469.2 C476.1 C504.1 C505.2 FB15.2 U32.D6(AGND_a) U32.E5(AGND_c) U32.E6(AGND_b) U32.F5(AGND_d) U32.G4(AGND_e) U32.H5(AGND_k) U32.H6(AGND_f) U32.J3(AGND_g) U32.J4(AGND_h) U32.J6(AGND_i) U32.K3(AGND_j) U32.M8(AGND2_b) U32.N8(AGND2_a)
AGND_XTAL: C127.1 C132.1 C472.1 FB13.1 U32.G7(REFGND)
DGND: C95.2 C96.2 C97.2 C98.2 C99.1 C101.2 C107.2 C108.2 C110.1 C111.1 C112.1 C114.1 C123.1 C124.1 C125.1 C126.1 C137.1 C138.1 C140.1 C141.1 C142.1 C148.1 C149.1 C150.1 C154.1 C155.1 C156.2 C439.2 C446.1 C463.1 C464.1 C468.2 C471.1 C479.1 C484.1 C485.2 C493.1 C498.2 C518.2 C519.2 C520.2 C533.2 C545.2 C711.1 C712.2 C713.1 C715.2 C717.1 C718.2 C720.1 C721.2 C723.1 C724.2 D12.2(A) D13.2(A) FB13.2 FB15.1 J17.1 J18.3 R244.2 R702.1 SW9.3(B1) SW9.4(B2) TP90.1(TP) TP92.1(TP) U22.9(EP) U32.A1(DGND_c) U32.A7(GND_CTRL_b) U32.A8(GND_CTRL_a) U32.B1(DGND_b) U32.B2(DGND_a) U32.C1(GND1_c) U32.C2(GND1_b) U32.D3(GND1_a) U32.J1(GND2_b) U32.J2(GND2_a) U32.J7(GNDIO_b) U32.J8(GNDIO_a) U42.1(A1) U42.2(A0) U42.7(GND) U43.1(A1) U43.7(GND) U44.1(A1) U44.7(GND) U46.1(A1) U46.7(GND) U48.2(A0) U48.7(GND) ; also on sheet 1 11 12 13 14 15 16 17 18 19 20 21 22 23 24 25 26 27 28 29 30 31 32 33 34 35 36 37 38 39 40 41 42 43 44 45 46 47 50
DVDD18: C722.2 J42.2 R381.1 U46.9(VIN-) ; also on sheet 13 14
DVDD33: C714.2 J39.2 R359.1 U42.9(VIN-) ; also on sheet 14
DVDD_DDR: C725.2 J43.2 R383.1 U48.9(VIN-) ; also on sheet 14
VCC3V3_DCIN: C107.1 C123.2 C124.2 C125.2 C126.2 C137.2 C138.2 C140.2 C463.2 C464.2 C479.2 C493.2 C498.1 C518.1 C519.1 C520.1 C533.1 C545.1 C711.2 C712.1 C713.2 C714.1 C717.2 C720.2 C723.2 J39.1 R253.2 R359.2 R371.1 R709.1 U32.D8(VCC5) U32.E1(VCC1_c) U32.F2(VCC1_b) U32.F3(VCC1_a) U32.G1(VCC2_b) U32.G2(VCC2_a) U32.N5(VCC6) U42.6(VS+) U42.8(VBUS) U42.10(VIN+) U43.2(A0) U43.6(VS+) U44.6(VS+) U46.6(VS+) U48.1(A1) U48.6(VS+) ; also on sheet 11 17 18 19 20 21 22 23 24 25 26 27 28 29 30 31 32 33 34 35 36 37 38 43 44 45 46 47 50
VCC5V0_DCDC: C108.1 C112.2 C114.2 C150.2 C154.2 C155.2 C156.1 C468.1 C471.2 C484.2 C485.1 J17.3 R334.1 R692.1 U32.A5(V5IN) U32.B6(VCC7) U32.L1(VCC4) U32.L7(VCCIO_b) U32.L8(VCCIO_a) U32.N3(VCC3) ; also on sheet 21 22 27 30 44 46 50
VCC12V0_DC_IN: C95.1 C96.1 C97.1 C98.1 C99.2 U22.1(VIN1) ; also on sheet 1 26 31 33 34 47 50
1P8V_EN: R338.2 R345.2 ; also on sheet 50
BMC_I2C0_SCL: R118.1 ; also on sheet 45
BMC_I2C0_SDA: R117.1 ; also on sheet 45
CLK32KOUT: R674.1 TP101.1(TP) U32.F4(CLK32KOUT)
CVDD: C451.2 C716.2 J40.2 R357.1 U32.B4(VOUT) U43.9(VIN-) ; also on sheet 13
CVDD1: C719.2 J41.2 R360.1 U44.9(VIN-) ; also on sheet 13
CVDD_EN: R340.2 R346.2
INA_ALERT: J18.4 R253.1 R788.1 R789.1 R790.1 R791.1 R792.1
LDO1_1V8: C152.2 C158.1 C721.1 C722.1 J42.1 R381.2 TP122.1(TP) U32.N6(LDO1) U46.8(VBUS) U46.10(VIN+) ; also on sheet 13 18 23 24 30 36
LDO2_1V8: C151.2 C157.1 TP118.1(TP) U32.N4(LDO2) ; also on sheet 23 24 30
LDO3_1V8: C457.1 C466.2 TP103.1(TP) U32.E7(LDO3) ; also on sheet 18 36
LDO4_1V8: C116.1 C121.2 TP100.1(TP) U32.C8(LDO4)
LDO5_3V3: C469.1 C476.2 TP110.1(TP) U32.K1(LDO5)
LDO6_3V3: C163.1 C164.2 TP120.1(TP) U32.M2(LDO6)
LDO7_3V3: C504.2 C505.1 TP121.1(TP) U32.M3(LDO7)
LDO8_3V3: C160.1 C161.2 TP119.1(TP) U32.M1(LDO8)
nRESPWRON2: R245.2 ; also on sheet 11 45
PMBUS_SCL: R118.2 R370.2 R709.2 U42.5(SCL) U43.5(SCL) U44.5(SCL) U46.2(A0) U46.5(SCL) U48.5(SCL)
PMBUS_SDA: R117.2 R371.2 R374.2 U42.4(SDA) U43.4(SDA) U44.2(A0) U44.4(SDA) U46.4(SDA) U48.4(SDA)
PMIC_GPIO2: R330.2 R703.2 ; also on sheet 50
PMIC_HDRST: D12.1(K) SW8.1(A1) SW8.2(A2) U32.L6(HDRST)
PMIC_PGOOD: TP85.1(TP) U32.C4(PGOOD)
PMIC_PWRHOLD: J13.2 U32.N1(PWRHOLD)
PMIC_PWRON: D13.1(K) R334.2 SW9.1(A1) SW9.2(A2) U32.E4(PWRON)
PMIC_VDD1: C110.2 C111.2 C718.1 C719.1 J41.1 L5.2 R360.2 U32.D4(VFB1) U44.8(VBUS) U44.10(VIN+)
PMIC_VDD2: C148.2 C149.2 C724.1 C725.1 J43.1 L7.2 R383.2 TP113.1(TP) U32.K2(VFB2) U48.8(VBUS) U48.10(VIN+) ; also on sheet 15 16 50
PMIC_VDD_CTRL: C101.1 C715.1 C716.1 J40.1 L4.2 R357.2 U43.8(VBUS) U43.10(VIN+)
PMIC_VIO: C141.2 C142.2 L6.2 R330.1 R345.1 R346.1 U32.H8(VFBIO) U32.N7(VDDIO) ; also on sheet 50
SOC_I2C2_SCL: R324.1 ; also on sheet 12 35
SOC_I2C2_SDA: R325.1 ; also on sheet 12 35
TPS_INT1: R341.2 ; also on sheet 12
TPS_SLEEP: U32.F1(SLEEP) ; also on sheet 12
VBACKUP: J17.2 U32.D7(VBACKUP)
VRTC: C439.1 C446.2 J13.1 R294.1 R668.1 R888.2 TP84.1(TP) U32.B5(VRTC)
WLAN_SLOW_CLK: R674.2 ; also on sheet 17 30
N17556024: R670.1 U32.A6(DRVL)
N17556030: C452.2 U22.4(TGR) U32.A4(SW)
N17556082: R244.1 U32.B3(TRIP)
N17556602: C452.1 U32.A2(VBST)
N17556776: R671.2 U22.3(TG)
N17556786: L5.1 U32.D1(SW1_c) U32.D2(SW1_b) U32.E2(SW1_a)
N17556798: L7.1 U32.H1(SW2_b) U32.H2(SW2_a)
N17556884: R671.1 U32.A3(DRVH)
N17556932: C451.1 U32.C5(VFB)
N17557226: TP91.1(TP) U32.C6(TRAN)
N17557396: TP102.1(TP) U32.D5(EN)
N17557440: L6.1 U32.K7(SWIO_b) U32.K8(SWIO_a)
N17557462: R670.2 U22.5(BG)
N17557538: R692.2 U32.E8(VCCS)
N19636064: R702.2 R888.1 U32.N2(PWRDN)
N19636076: C472.2 TP109.1(TP) U32.G8(VREF)
N19636197: R668.2 U32.J5(BOOT1)
N19636243: R298.2 U32.F8(OSC32KIN)
N19636273: R284.2 U32.F7(OSC32KOUT)
N19636291: C127.2 R284.1 Y4.1
N19636350: C132.2 R298.1 Y4.2
N19636388: TP114.1(TP) U32.M6(EN2)
N19636390: TP116.1(TP) U32.M7(EN1)
N19636467: R325.2 U32.M5(SDA)
N19636469: R324.2 U32.M4(SCL)
N19643422: J18.2 R374.1
N19643490: J18.1 R370.1
N19723053: L4.1 U22.6(VSW) U22.7(VSW) U22.8(VSW)
N20088340: R703.1 U32.L2(GPIO2)
N20088352: R340.1 U32.G3(GPIO6)
N20088355: R338.1 U32.L4(GPIO7)
N20088489: TP112.1(TP) U32.H4(NRESPWRON1)
N20088492: R245.1 U32.C7(NRESPWRON2)
N20088495: R341.1 U32.L3(INT1)
N21316200: R294.2 SW8.3(B1) SW8.4(B2)
N21783594: R788.2 U42.3(ALERT)
N21786150: R789.2 U43.3(ALERT)
N21786851: R792.2 U48.3(ALERT)
N21787536: R790.2 U44.3(ALERT)
N21787552: R791.2 U46.3(ALERT)
N22774183: TP175.1(TP) U32.L5(GPIO0)
N22774186: TP107.1(TP) U32.F6(GPIO1)
N22774189: TP111.1(TP) U32.G6(GPIO5)
N22774190: TP108.1(TP) U32.H7(GPIO4)
N22774191: TP88.1(TP) U32.B7(GPIO3)
N22774198: TP117.1(TP) U32.K5(GPIO8)
N29294378: TP89.1(TP) U32.B8(TEST)

Not connected (* = marked no-connect by the designer): J18 5*

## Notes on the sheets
sheet 48
- PMIC POWER SECTION 1
- I2C ADDRESS:
  0x40 : 3.3V
- I2C ADDRESS:
  0x41 : CVDD
- INA DEVICES
- I2C ADDRESS:
  0x42 : CVDD1
- I2C ADDRESS:
  0x43 : 1.8V
- I2C ADDRESS:
  0x44 : DVDD_DDR
sheet 49
- PMIC POWER SECTION 2
- PMIC RST
- PMIC PWRON
- I2C ADDRESS: 0x2D (GENERAL PURPOSE) TBD
                            0x12 (VOLTAGE SCALING) TBD
